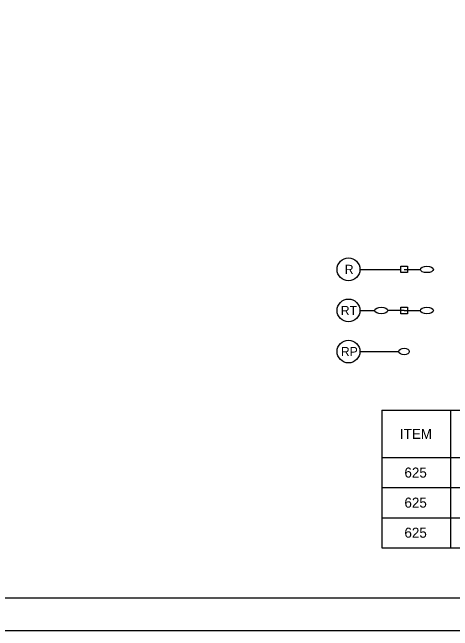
# Model space of a CAD drawing. Extents: x -0.1 to 34, y 0 to 22.
# Drawn here: x 16.94 to 23.7, y 0 to 9.48 of the extents above; entities that cross this region are included whole.
import ezdxf

# ---------------------------------------------------------------- set-up
doc = ezdxf.new("R2010")
doc.units = 0
for name, color, linetype in [('Default', 7, 'Continuous'), ('LT_X_Luminaires', 7, 'Continuous'), ('SH_Border', 7, 'Continuous'), ('SH_Cut_Line', 7, 'Continuous'), ('SH_Text', 7, 'Continuous')]:
    doc.layers.add(name, color=color, linetype=linetype)

msp = doc.modelspace()

# ---------------------------------------------------------------- linework, layer by layer
at = {"layer": 'Default'}
for p, q in [((22.6167, 3.38), (30.7038, 3.38)), ((22.6167, 3.38), (22.6167, 1.2717)), ((23.6709, 3.38), (23.6709, 1.2717)), ((22.6167, 2.6553), (30.7038, 2.6553)), ((22.6167, 2.1941), (30.7038, 2.1941)), ((22.6167, 1.7329), (30.7038, 1.7329)), ((22.6167, 1.2717), (30.7038, 1.2717))]:
    msp.add_line(p, q, dxfattribs=at)
at = {"layer": 'LT_X_Luminaires'}
for p, q in [((22.9569, 5.5415), (23.2069, 5.5416)), ((22.9569, 4.9116), (22.7069, 4.9115)), ((22.9569, 4.9116), (23.2069, 4.9116))]:
    msp.add_line(p, q, dxfattribs=at)
for points in [[(22.9069, 5.5915), (23.0069, 5.5916), (23.0069, 5.4916), (22.9069, 5.4915)], [(22.9069, 4.9615), (23.0069, 4.9616), (23.0069, 4.8616), (22.9069, 4.8615)], [(23.0069, 4.8616), (22.9069, 4.8615), (22.9069, 4.9615), (23.0069, 4.9616)]]:
    msp.add_lwpolyline(points, close=True, dxfattribs=at)
for centre, major_axis, ratio in [((23.3069, 5.5415), (0.1, 0), 0.5), ((22.6069, 4.9116), (-0.1, 0), 0.5), ((23.3069, 4.9115), (0.1, 0), 0.5), ((22.9569, 4.2816), (0.08, 0), 0.625)]:
    msp.add_ellipse(centre, major_axis=major_axis, ratio=ratio, dxfattribs=at)
at = {"layer": 'SH_Border'}
msp.add_lwpolyline([(1.5, 21.5), (33.5, 21.5), (33.5, 0.5), (1.5, 0.5)], close=True, dxfattribs=at)
at = {"layer": 'SH_Cut_Line'}
msp.add_lwpolyline([(0, 0), (34, 0), (34, 22), (0, 22)], close=True, dxfattribs=at)
at = {"layer": 'SH_Text'}
for p, q in [((22.2782, 5.5415), (22.9069, 5.5415)), ((22.2782, 4.9115), (22.5069, 4.9116)), ((22.2782, 4.2815), (22.8769, 4.2815))]:
    msp.add_line(p, q, dxfattribs=at)
for centre in [(22.103, 5.5415), (22.103, 4.9115), (22.103, 4.2815)]:
    msp.add_circle(centre, 0.1752, dxfattribs=at)

# ---------------------------------------------------------------- texts
at = {"layer": 'Default'}
for s, p in [('ITEM', (22.8923, 2.9406)), ('625', (22.962, 2.3477)), ('625', (22.962, 1.8865)), ('625', (22.962, 1.4253))]:
    msp.add_text(s, height=0.154, dxfattribs=at).set_placement(p)
at = {"layer": 'SH_Text'}
for s, p in [('R', (22.0458, 5.4715)), ('RT', (21.9844, 4.8415)), ('RP', (21.9858, 4.2115))]:
    msp.add_text(s, height=0.14, dxfattribs=at).set_placement(p)

doc.saveas('drawing.dxf')
